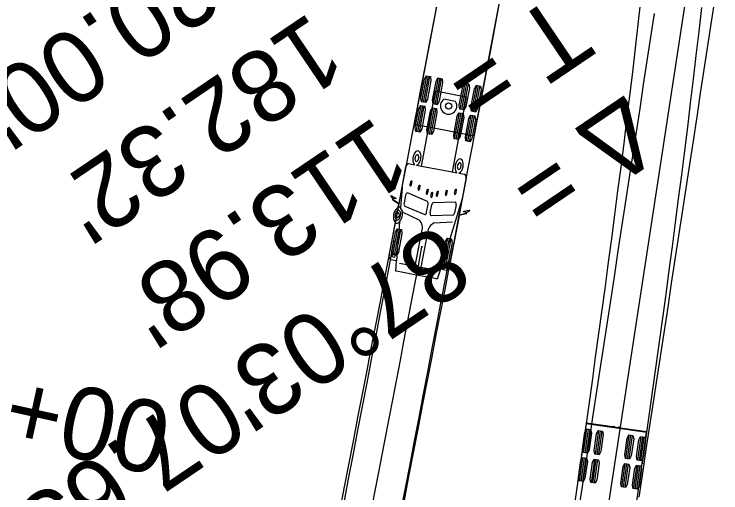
# Model space of a CAD drawing. Extents: x -69 to 14108008, y -6 to 8640172.
# Drawn here: x 14107816.5 to 14107914.7, y 8639651.1 to 8639717.5 of the extents above; entities that cross this region are included whole.
import ezdxf

# ---------------------------------------------------------------- set-up
doc = ezdxf.new("R2010")
doc.units = 0
for name, color, linetype in [('AutoTurn', 7, 'Continuous'), ('AutoTurn1', 7, 'Continuous'), ('AutoTurn2', 7, 'Continuous'), ('TextAlignment', 7, 'Continuous'), ('TextAlignmentSml', 7, 'Continuous')]:
    doc.layers.add(name, color=color, linetype=linetype)

msp = doc.modelspace()

# ---------------------------------------------------------------- linework, layer by layer
at = {"layer": 'AutoTurn'}
msp.add_arc((14098576.761, 8641447.78), 9462, 348.2293605, 349.264447, dxfattribs=at)
at = {"layer": 'AutoTurn1'}
for p, q in [((14107873.128, 8639705.357), (14107873.811, 8639708.959)), ((14107873.354, 8639705.314), (14107874.037, 8639708.916)), ((14107873.579, 8639705.271), (14107874.262, 8639708.874)), ((14107874.75, 8639705.049), (14107875.433, 8639708.652)), ((14107874.975, 8639705.007), (14107875.658, 8639708.609)), ((14107875.2, 8639704.964), (14107875.883, 8639708.566)), ((14107878.467, 8639704.345), (14107879.15, 8639707.947)), ((14107878.692, 8639704.302), (14107879.375, 8639707.904)), ((14107878.917, 8639704.259), (14107879.6, 8639707.862)), ((14107880.088, 8639704.037), (14107880.771, 8639707.64)), ((14107880.313, 8639703.995), (14107880.996, 8639707.597)), ((14107880.538, 8639703.952), (14107881.221, 8639707.554)), ((14107877.796, 8639705.42), (14107876.208, 8639705.721)), ((14107872.346, 8639701.23), (14107873.029, 8639704.833)), ((14107872.571, 8639701.187), (14107873.254, 8639704.79)), ((14107872.796, 8639701.145), (14107873.479, 8639704.747)), ((14107873.967, 8639700.923), (14107874.65, 8639704.525)), ((14107874.192, 8639700.88), (14107874.875, 8639704.483)), ((14107874.418, 8639700.837), (14107875.101, 8639704.44)), ((14107877.684, 8639700.218), (14107878.367, 8639703.821)), ((14107877.91, 8639700.175), (14107878.593, 8639703.778)), ((14107878.135, 8639700.133), (14107878.818, 8639703.735)), ((14107879.305, 8639699.911), (14107879.988, 8639703.513)), ((14107879.531, 8639699.868), (14107880.214, 8639703.471)), ((14107879.756, 8639699.825), (14107880.439, 8639703.428)), ((14107871.291, 8639696.782), (14107872.122, 8639696.625)), ((14107873.073, 8639696.444), (14107877.328, 8639695.638)), ((14107878.279, 8639695.457), (14107879.109, 8639695.3)), ((14107871.505, 8639693.868), (14107871.646, 8639694.401)), ((14107871.646, 8639694.401), (14107871.735, 8639694.384)), ((14107871.735, 8639694.384), (14107871.671, 8639693.837)), ((14107872.63, 8639693.263), (14107872.771, 8639693.795)), ((14107872.771, 8639693.795), (14107872.859, 8639693.779)), ((14107872.859, 8639693.779), (14107872.795, 8639693.231)), ((14107870.384, 8639693.454), (14107870.178, 8639690.655)), ((14107873.764, 8639692.707), (14107873.905, 8639693.24)), ((14107873.905, 8639693.24), (14107873.993, 8639693.223)), ((14107873.993, 8639693.223), (14107873.929, 8639692.676)), ((14107874.4, 8639692.273), (14107874.541, 8639692.805)), ((14107874.541, 8639692.805), (14107874.629, 8639692.789)), ((14107875.152, 8639692.444), (14107875.293, 8639692.977)), ((14107875.293, 8639692.977), (14107875.381, 8639692.96)), ((14107875.381, 8639692.96), (14107875.317, 8639692.413)), ((14107876.406, 8639692.521), (14107876.551, 8639693.079)), ((14107876.551, 8639693.079), (14107876.639, 8639693.062)), ((14107876.639, 8639693.062), (14107876.572, 8639692.49)), ((14107877.678, 8639692.698), (14107877.819, 8639693.231)), ((14107877.819, 8639693.231), (14107877.907, 8639693.214)), ((14107877.907, 8639693.214), (14107877.843, 8639692.667)), ((14107869.142, 8639691.932), (14107869.123, 8639691.952)), ((14107869.17, 8639691.928), (14107869.142, 8639691.932)), ((14107870.886, 8639692.391), (14107870.676, 8639691.28)), ((14107873.914, 8639691.537), (14107871.15, 8639692.717)), ((14107874.629, 8639692.789), (14107874.566, 8639692.241)), ((14107878.735, 8639691.871), (14107875.708, 8639682.13)), ((14107869.965, 8639691.244), (14107869.946, 8639691.145)), ((14107870.769, 8639690.885), (14107873.534, 8639689.705)), ((14107873.797, 8639690.032), (14107874.008, 8639691.143)), ((14107874.306, 8639689.935), (14107874.517, 8639691.046)), ((14107874.748, 8639691.379), (14107877.753, 8639691.466)), ((14107877.879, 8639691.065), (14107877.668, 8639689.954)), ((14107872.766, 8639688.943), (14107870.448, 8639690.03)), ((14107879.307, 8639690.006), (14107879.334, 8639689.999)), ((14107879.334, 8639689.999), (14107879.359, 8639690.011)), ((14107877.437, 8639689.621), (14107874.432, 8639689.535)), ((14107878.316, 8639689.66), (14107878.298, 8639689.562)), ((14107868.593, 8639684.008), (14107869.458, 8639688.571)), ((14107870.034, 8639688.693), (14107869.636, 8639683.281)), ((14107874.867, 8639688.544), (14107877.409, 8639688.706)), ((14107869.105, 8639684.135), (14107869.788, 8639687.737)), ((14107869.33, 8639684.092), (14107870.013, 8639687.695)), ((14107869.555, 8639684.049), (14107870.238, 8639687.652)), ((14107872.22, 8639682.562), (14107873.131, 8639687.367)), ((14107873.04, 8639682.406), (14107873.951, 8639687.212)), ((14107876.064, 8639682.815), (14107876.747, 8639686.418)), ((14107876.289, 8639682.773), (14107876.972, 8639686.375)), ((14107876.515, 8639682.73), (14107877.198, 8639686.332)), ((14107869.054, 8639684.242), (14107868.988, 8639683.892)), ((14107869.459, 8639684.165), (14107869.054, 8639684.242)), ((14107869.393, 8639683.815), (14107869.459, 8639684.165)), ((14107868.988, 8639683.892), (14107869.393, 8639683.815)), ((14107870.039, 8639682.975), (14107875.505, 8639681.939)), ((14107876.129, 8639682.538), (14107876.196, 8639682.888)), ((14107876.535, 8639682.461), (14107876.129, 8639682.538)), ((14107876.196, 8639682.888), (14107876.601, 8639682.811)), ((14107876.601, 8639682.811), (14107876.535, 8639682.461))]:
    msp.add_line(p, q, dxfattribs=at)
for points in [[(14107881.931, 8639754.235), (14107881.909, 8639754.239), (14107881.896, 8639754.17), (14107880.84, 8639748.602), (14107872.049, 8639702.236), (14107876.225, 8639701.445), (14107880.4, 8639700.653), (14107889.191, 8639747.019), (14107890.246, 8639752.587), (14107890.259, 8639752.656), (14107890.238, 8639752.66)], [(14107875.495, 8639720.425), (14107874.873, 8639717.152), (14107874.251, 8639713.879), (14107873.628, 8639710.606), (14107873.005, 8639707.333), (14107872.382, 8639704.061), (14107871.758, 8639700.788), (14107871.134, 8639697.516), (14107870.509, 8639694.244), (14107869.883, 8639690.972), (14107869.257, 8639687.7), (14107868.63, 8639684.428), (14107868.002, 8639681.157), (14107867.374, 8639677.886), (14107866.744, 8639674.615), (14107866.114, 8639671.344), (14107865.484, 8639668.073), (14107864.852, 8639664.802), (14107864.22, 8639661.532), (14107863.586, 8639658.262), (14107862.952, 8639654.992), (14107862.317, 8639651.722), (14107861.681, 8639648.453)], [(14107883.846, 8639718.839), (14107883.224, 8639715.565), (14107882.601, 8639712.291), (14107881.979, 8639709.017), (14107881.355, 8639705.744), (14107880.732, 8639702.47), (14107880.108, 8639699.196), (14107879.483, 8639695.922), (14107878.857, 8639692.648), (14107878.232, 8639689.375), (14107877.605, 8639686.101), (14107876.978, 8639682.828), (14107876.35, 8639679.555), (14107875.721, 8639676.281), (14107875.091, 8639673.008), (14107874.461, 8639669.735), (14107873.83, 8639666.462), (14107873.198, 8639663.19), (14107872.565, 8639659.917), (14107871.931, 8639656.645), (14107871.296, 8639653.372), (14107870.661, 8639650.1)], [(14107872.399, 8639696.572), (14107873.072, 8639696.444), (14107873.117, 8639696.678), (14107875.048, 8639706.859), (14107877.175, 8639706.455), (14107879.302, 8639706.052), (14107877.372, 8639695.872), (14107877.328, 8639695.638), (14107878.002, 8639695.51)], [(14107869.107, 8639691.866), (14107869.123, 8639691.951), (14107869.121, 8639691.954), (14107868.854, 8639692.247), (14107868.852, 8639692.249), (14107868.874, 8639692.366), (14107868.876, 8639692.366), (14107869.535, 8639691.979), (14107869.516, 8639691.878), (14107869.17, 8639691.928), (14107869.169, 8639691.927), (14107869.155, 8639691.848), (14107869.155, 8639691.847), (14107869.155, 8639691.847), (14107869.16, 8639691.809), (14107869.16, 8639691.808), (14107869.965, 8639691.244), (14107870.929, 8639696.329)], [(14107879.281, 8639694.746), (14107878.316, 8639689.66), (14107879.272, 8639689.891), (14107879.272, 8639689.892), (14107879.291, 8639689.925), (14107879.291, 8639689.926), (14107879.291, 8639689.927), (14107879.307, 8639690.005), (14107879.306, 8639690.006), (14107878.967, 8639690.086), (14107878.986, 8639690.188), (14107879.741, 8639690.306), (14107879.742, 8639690.305), (14107879.72, 8639690.189), (14107879.718, 8639690.187), (14107879.361, 8639690.012), (14107879.359, 8639690.01), (14107879.342, 8639689.926)], [(14107869.866, 8639690.719), (14107869.945, 8639691.137), (14107869.938, 8639691.151), (14107869.126, 8639691.727)], [(14107879.274, 8639689.803), (14107878.307, 8639689.564), (14107878.296, 8639689.554), (14107876.945, 8639682.424)], [(14107869.221, 8639685.979), (14107868.6, 8639682.705), (14107867.978, 8639679.432), (14107867.354, 8639676.16), (14107866.73, 8639672.888), (14107866.104, 8639669.616), (14107865.477, 8639666.344), (14107864.849, 8639663.073), (14107864.22, 8639659.802), (14107863.59, 8639656.531), (14107862.958, 8639653.26), (14107862.326, 8639649.99), (14107861.692, 8639646.72), (14107861.057, 8639643.45), (14107860.421, 8639640.181), (14107859.784, 8639636.912), (14107859.146, 8639633.642), (14107858.506, 8639630.374), (14107857.866, 8639627.105), (14107857.224, 8639623.837), (14107856.581, 8639620.569), (14107855.937, 8639617.301), (14107855.292, 8639614.033)], [(14107877.081, 8639684.488), (14107876.46, 8639681.214), (14107875.837, 8639677.94), (14107875.214, 8639674.666), (14107874.589, 8639671.393), (14107873.963, 8639668.119), (14107873.336, 8639664.845), (14107872.707, 8639661.572), (14107872.078, 8639658.299), (14107871.447, 8639655.026), (14107870.815, 8639651.753), (14107870.182, 8639648.48), (14107869.548, 8639645.208), (14107868.912, 8639641.935), (14107868.276, 8639638.663), (14107867.638, 8639635.391), (14107867, 8639632.12), (14107866.36, 8639628.848), (14107865.718, 8639625.577), (14107865.076, 8639622.306), (14107864.433, 8639619.035), (14107863.788, 8639615.765)], [(14107876.558, 8639681.968), (14107875.716, 8639682.128), (14107875.707, 8639682.128), (14107875.281, 8639680.759), (14107875.219, 8639680.77), (14107872.406, 8639681.304), (14107869.593, 8639681.837), (14107869.531, 8639681.849), (14107869.636, 8639683.279), (14107869.628, 8639683.282), (14107868.786, 8639683.442)]]:
    msp.add_lwpolyline(points, dxfattribs=at)
for points in [[(14107873.635, 8639705.261), (14107873.073, 8639705.367), (14107872.999, 8639705.904), (14107873.491, 8639708.497), (14107873.756, 8639708.97), (14107874.318, 8639708.863), (14107874.391, 8639708.327), (14107873.9, 8639705.733)], [(14107875.256, 8639704.953), (14107874.694, 8639705.06), (14107874.62, 8639705.596), (14107875.112, 8639708.19), (14107875.377, 8639708.662), (14107875.939, 8639708.556), (14107876.012, 8639708.019), (14107875.521, 8639705.426)], [(14107878.973, 8639704.249), (14107878.411, 8639704.355), (14107878.337, 8639704.892), (14107878.829, 8639707.485), (14107879.094, 8639707.958), (14107879.656, 8639707.851), (14107879.73, 8639707.315), (14107879.238, 8639704.721)], [(14107880.594, 8639703.941), (14107880.032, 8639704.048), (14107879.958, 8639704.584), (14107880.45, 8639707.178), (14107880.715, 8639707.65), (14107881.277, 8639707.544), (14107881.351, 8639707.007), (14107880.859, 8639704.413)], [(14107872.852, 8639701.134), (14107872.29, 8639701.241), (14107872.217, 8639701.777), (14107872.708, 8639704.371), (14107872.973, 8639704.843), (14107873.535, 8639704.737), (14107873.609, 8639704.2), (14107873.117, 8639701.606)], [(14107874.473, 8639700.827), (14107873.911, 8639700.933), (14107873.838, 8639701.47), (14107874.329, 8639704.064), (14107874.594, 8639704.536), (14107875.156, 8639704.429), (14107875.23, 8639703.893), (14107874.738, 8639701.299)], [(14107878.191, 8639700.122), (14107877.629, 8639700.229), (14107877.555, 8639700.765), (14107878.047, 8639703.359), (14107878.312, 8639703.831), (14107878.874, 8639703.725), (14107878.947, 8639703.188), (14107878.455, 8639700.594)], [(14107879.812, 8639699.815), (14107879.25, 8639699.921), (14107879.176, 8639700.458), (14107879.668, 8639703.052), (14107879.933, 8639703.524), (14107880.495, 8639703.417), (14107880.568, 8639702.881), (14107880.077, 8639700.287)], [(14107869.611, 8639684.039), (14107869.049, 8639684.145), (14107868.975, 8639684.682), (14107869.467, 8639687.276), (14107869.732, 8639687.748), (14107870.294, 8639687.641), (14107870.368, 8639687.105), (14107869.876, 8639684.511)], [(14107876.57, 8639682.719), (14107876.008, 8639682.826), (14107875.935, 8639683.362), (14107876.427, 8639685.956), (14107876.691, 8639686.428), (14107877.253, 8639686.322), (14107877.327, 8639685.785), (14107876.835, 8639683.192)]]:
    msp.add_lwpolyline(points, close=True, dxfattribs=at)
for centre, radius in [((14107876.856, 8639704.774), 0.424), ((14107869.221, 8639685.979), 0.0417), ((14107873.151, 8639685.234), 0.0417), ((14107877.081, 8639684.488), 0.0417)]:
    msp.add_circle(centre, radius, dxfattribs=at)
for centre, radius, start, end in [((14107876.851, 8639704.777), 1.143, 124.26445, 34.26445), ((14107873.3, 8639697.433), 1.416, 134.26844, 171.3363), ((14107872.845, 8639697.498), 0.664, 136.1389, 174.36062), ((14107872.56, 8639698.206), 0.346, 38.85869, 135.87175), ((14107872.496, 8639697.845), 0.172, 51.81225, 138.96284), ((14107872.346, 8639697.725), 0.362, 355.9269, 44.96789), ((14107871.882, 8639697.796), 1.136, 351.97974, 33.50048), ((14107871.537, 8639696.214), 0.619, 113.42476, 169.26647), ((14107872.997, 8639697.349), 1.136, 164.84322, 219.63451), ((14107872.693, 8639697.446), 0.522, 167.09496, 214.25908), ((14107872.389, 8639697.262), 0.169, 220.7114, 320.83012), ((14107872.138, 8639697.253), 0.729, 290.94196, 333.45596), ((14107871.977, 8639697.647), 0.732, 317.85619, 4.09062), ((14107871.282, 8639697.776), 1.73, 330.6393, 355.43781), ((14107879.482, 8639696.221), 1.73, 163.09109, 187.88959), ((14107878.931, 8639696.46), 1.136, 125.02841, 166.54916), ((14107878.473, 8639696.563), 0.362, 113.56101, 162.60199), ((14107878.45, 8639697.09), 0.346, 22.65715, 119.6702), ((14107878.378, 8639696.73), 0.172, 19.56605, 106.71664), ((14107877.925, 8639696.534), 0.664, 344.16828, 22.38999), ((14107877.478, 8639696.641), 1.416, 347.1926, 24.26045), ((14107878.494, 8639696.048), 0.729, 185.07293, 227.58693), ((14107878.787, 8639696.355), 0.732, 154.43827, 200.67271), ((14107878.263, 8639696.148), 0.169, 197.69877, 297.81749), ((14107877.73, 8639696.452), 1.136, 298.89438, 353.68568), ((14107878.048, 8639696.431), 0.522, 304.26981, 351.43394), ((14107878.672, 8639694.861), 0.619, 349.26242, 45.10413), ((14107871.639, 8639693.787), 0.157, 148.6088, 235.71847), ((14107871.487, 8639693.83), 0.184, 290.41925, 2.31127), ((14107872.764, 8639693.181), 0.157, 148.6088, 235.71847), ((14107872.611, 8639693.224), 0.184, 290.41925, 2.31127), ((14107869.18, 8639691.787), 0.108, 132.24078, 178.42327), ((14107871.218, 8639692.393), 0.332, 101.92104, 180.34304), ((14107873.898, 8639692.626), 0.157, 148.6088, 235.71847), ((14107873.745, 8639692.669), 0.184, 290.41925, 2.31127), ((14107874.534, 8639692.191), 0.157, 148.6088, 235.71847), ((14107874.411, 8639692.214), 0.157, 282.81043, 9.92009), ((14107875.32, 8639692.37), 0.184, 156.21763, 228.10964), ((14107875.163, 8639692.386), 0.157, 282.81043, 9.92009), ((14107876.579, 8639692.472), 0.184, 156.21763, 228.10964), ((14107876.421, 8639692.488), 0.157, 282.81043, 9.92009), ((14107877.847, 8639692.624), 0.184, 156.21763, 228.10964), ((14107877.689, 8639692.64), 0.157, 282.81043, 9.92009), ((14107869.123, 8639691.779), 0.0522, 168.14704, 273.00166), ((14107871.043, 8639691.158), 0.387, 161.69963, 224.9316), ((14107873.641, 8639691.264), 0.387, 341.70208, 44.92915), ((14107874.903, 8639691.025), 0.387, 113.59975, 176.82681), ((14107877.57, 8639691.188), 0.332, 338.18585, 56.60785), ((14107870.715, 8639689.444), 1.53, 123.75718, 214.76623), ((14107870.467, 8639689.521), 1.03, 142.0881, 170.47461), ((14107870.207, 8639689.543), 0.589, 142.01997, 185.00269), ((14107869.919, 8639689.98), 0.317, 85.11464, 146.70704), ((14107869.875, 8639689.799), 0.17, 86.93351, 140.99785), ((14107869.963, 8639690.383), 0.347, 51.59166, 106.40224), ((14107869.761, 8639689.737), 0.263, 348.19936, 62.10128), ((14107869.759, 8639689.896), 0.44, 1.05869, 64.87154), ((14107869.017, 8639689.774), 1.189, 330.39565, 6.28497), ((14107869.331, 8639689.898), 1.136, 347.96899, 41.77155), ((14107873.503, 8639689.999), 0.296, 275.98321, 6.28088), ((14107874.568, 8639689.797), 0.296, 152.24801, 242.54569), ((14107877.282, 8639689.975), 0.387, 293.5973, 356.82926), ((14107879.246, 8639689.878), 0.108, 340.10562, 26.28812), ((14107870.047, 8639689.473), 0.634, 159.84831, 235.85002), ((14107869.843, 8639689.478), 0.223, 176.49935, 246.10184), ((14107869.708, 8639689.313), 0.366, 267.31679, 339.79777), ((14107869.768, 8639689.431), 0.158, 264.23567, 325.74842), ((14107869.443, 8639689.694), 0.575, 322.33956, 358.90989), ((14107868.745, 8639689.807), 1.704, 319.18513, 355.0932), ((14107871.699, 8639687.865), 1.517, 340.84449, 45.27191), ((14107879.296, 8639689.85), 0.0522, 245.52723, 350.38185), ((14107869.691, 8639688.944), 0.425, 237.32738, 323.86374), ((14107875.466, 8639687.151), 1.517, 113.25699, 177.6844), ((14098576.761, 8641447.78), 9462, 348.2293605, 349.264447), ((14107869.052, 8639683.849), 0.486, 160.85038, 236.80148), ((14107876.459, 8639682.444), 0.486, 281.72741, 357.67852)]:
    msp.add_arc(centre, radius, start, end, dxfattribs=at)
for centre, major_axis, start_param, end_param in [((14107869.116, 8639691.796), (-0.0146, -0.0769), 2.398717, 3.668019), ((14107869.116, 8639691.796), (-0.0146, -0.0769), 0.569648, 1.840391), ((14107879.309, 8639689.863), (0.0146, 0.0769), 1.301202, 2.571945), ((14107879.309, 8639689.863), (-0.0146, -0.0769), 2.615166, 3.884468)]:
    msp.add_ellipse(centre, major_axis=major_axis, ratio=0.544872, start_param=start_param, end_param=end_param, dxfattribs=at)
at = {"layer": 'AutoTurn2'}
for p, q in [((14107922.677, 8639804.377), (14107890.191, 8639591.46)), ((14107895.936, 8639660.698), (14107904.352, 8639659.503)), ((14107895.599, 8639656.697), (14107896.063, 8639659.964)), ((14107895.826, 8639656.665), (14107896.29, 8639659.932)), ((14107896.053, 8639656.632), (14107896.517, 8639659.9)), ((14107897.233, 8639656.465), (14107897.697, 8639659.732)), ((14107897.46, 8639656.433), (14107897.924, 8639659.7)), ((14107897.687, 8639656.4), (14107898.151, 8639659.668)), ((14107899.628, 8639660.245), (14107899.891, 8639660.208)), ((14107900.41, 8639660.134), (14107899.894, 8639660.207)), ((14107900.154, 8639660.17), (14107900.144, 8639660.1)), ((14107900.417, 8639660.133), (14107900.68, 8639660.096)), ((14107901.474, 8639655.862), (14107901.938, 8639659.13)), ((14107901.701, 8639655.83), (14107902.165, 8639659.097)), ((14107901.928, 8639655.798), (14107902.392, 8639659.065)), ((14107903.107, 8639655.63), (14107903.571, 8639658.898)), ((14107903.334, 8639655.598), (14107903.798, 8639658.865)), ((14107903.561, 8639655.566), (14107904.025, 8639658.833)), ((14107895.037, 8639652.737), (14107895.501, 8639656.004)), ((14107895.264, 8639652.704), (14107895.728, 8639655.972)), ((14107895.491, 8639652.672), (14107895.955, 8639655.939)), ((14107896.67, 8639652.505), (14107897.135, 8639655.772)), ((14107896.897, 8639652.472), (14107897.361, 8639655.74)), ((14107897.124, 8639652.44), (14107897.588, 8639655.707)), ((14107900.911, 8639651.902), (14107901.375, 8639655.169)), ((14107901.138, 8639651.87), (14107901.602, 8639655.137)), ((14107901.365, 8639651.838), (14107901.829, 8639655.105)), ((14107902.545, 8639651.67), (14107903.009, 8639654.937)), ((14107902.772, 8639651.638), (14107903.236, 8639654.905)), ((14107902.999, 8639651.606), (14107903.463, 8639654.873))]:
    msp.add_line(p, q, dxfattribs=at)
for points in [[(14107903.503, 8639719.381), (14107903.133, 8639716.083), (14107902.754, 8639712.784), (14107902.367, 8639709.486), (14107901.971, 8639706.187), (14107901.568, 8639702.888), (14107901.158, 8639699.589), (14107900.741, 8639696.29), (14107900.318, 8639692.992), (14107899.89, 8639689.693), (14107899.456, 8639686.395), (14107899.017, 8639683.096), (14107898.574, 8639679.798), (14107898.127, 8639676.5), (14107897.676, 8639673.202), (14107897.221, 8639669.903), (14107896.763, 8639666.606), (14107896.301, 8639663.308), (14107895.837, 8639660.01), (14107895.37, 8639656.712), (14107895.323, 8639656.383)], [(14107913.809, 8639719.738), (14107913.306, 8639716.441), (14107912.803, 8639713.143), (14107912.3, 8639709.846), (14107911.797, 8639706.549), (14107911.294, 8639703.252), (14107910.791, 8639699.956), (14107910.288, 8639696.659), (14107909.785, 8639693.363), (14107909.282, 8639690.066), (14107908.779, 8639686.77), (14107908.276, 8639683.474), (14107907.773, 8639680.178), (14107907.27, 8639676.882), (14107906.768, 8639673.586), (14107906.265, 8639670.289), (14107905.762, 8639666.993), (14107905.259, 8639663.697), (14107904.756, 8639660.401), (14107904.253, 8639657.105), (14107903.75, 8639653.809), (14107903.247, 8639650.513)], [(14107911.951, 8639718.449), (14107911.579, 8639715.126), (14107911.198, 8639711.804), (14107910.808, 8639708.484), (14107910.409, 8639705.166), (14107910.004, 8639701.849), (14107909.592, 8639698.533), (14107909.173, 8639695.218), (14107908.748, 8639691.905), (14107908.318, 8639688.592), (14107907.883, 8639685.281), (14107907.443, 8639681.971), (14107906.998, 8639678.661), (14107906.549, 8639675.353), (14107906.097, 8639672.045), (14107905.641, 8639668.738), (14107905.181, 8639665.432), (14107904.719, 8639662.127), (14107904.254, 8639658.822), (14107903.786, 8639655.518), (14107903.739, 8639655.187)], [(14107905.395, 8639717.629), (14107904.892, 8639714.335), (14107904.39, 8639711.04), (14107903.887, 8639707.745), (14107903.384, 8639704.45), (14107902.881, 8639701.155), (14107902.379, 8639697.859), (14107901.876, 8639694.564), (14107901.373, 8639691.268), (14107900.87, 8639687.973), (14107900.367, 8639684.677), (14107899.864, 8639681.382), (14107899.362, 8639678.086), (14107898.859, 8639674.79), (14107898.356, 8639671.494), (14107897.853, 8639668.199), (14107897.35, 8639664.903), (14107896.847, 8639661.607), (14107896.344, 8639658.311), (14107895.842, 8639655.015), (14107895.339, 8639651.719), (14107894.836, 8639648.424)], [(14107895.968, 8639660.765), (14107895.947, 8639660.768), (14107895.937, 8639660.698), (14107895.139, 8639655.087), (14107888.502, 8639608.365), (14107892.71, 8639607.767), (14107896.918, 8639607.169), (14107903.555, 8639653.892), (14107904.351, 8639659.503), (14107904.361, 8639659.573), (14107904.34, 8639659.576)], [(14107899.904, 8639660.277), (14107899.639, 8639660.315), (14107899.638, 8639660.314), (14107899.628, 8639660.245), (14107899.593, 8639660.25), (14107895.993, 8639660.761), (14107895.992, 8639660.762)], [(14107904.316, 8639659.579), (14107904.315, 8639659.579), (14107900.715, 8639660.091), (14107900.68, 8639660.096), (14107900.69, 8639660.165), (14107900.688, 8639660.166), (14107900.424, 8639660.203)]]:
    msp.add_lwpolyline(points, dxfattribs=at)
for points in [[(14107896.109, 8639656.624), (14107895.543, 8639656.705), (14107895.437, 8639657.187), (14107895.772, 8639659.539), (14107896.007, 8639659.972), (14107896.574, 8639659.892), (14107896.679, 8639659.41), (14107896.345, 8639657.058)], [(14107897.743, 8639656.392), (14107897.177, 8639656.473), (14107897.071, 8639656.954), (14107897.405, 8639659.307), (14107897.641, 8639659.74), (14107898.207, 8639659.66), (14107898.313, 8639659.178), (14107897.979, 8639656.826)], [(14107901.984, 8639655.79), (14107901.417, 8639655.87), (14107901.312, 8639656.352), (14107901.646, 8639658.704), (14107901.882, 8639659.138), (14107902.448, 8639659.057), (14107902.554, 8639658.576), (14107902.219, 8639656.223)], [(14107903.617, 8639655.558), (14107903.051, 8639655.638), (14107902.945, 8639656.12), (14107903.28, 8639658.472), (14107903.515, 8639658.906), (14107904.081, 8639658.825), (14107904.187, 8639658.344), (14107903.853, 8639655.991)], [(14107895.547, 8639652.664), (14107894.981, 8639652.745), (14107894.875, 8639653.226), (14107895.209, 8639655.579), (14107895.445, 8639656.012), (14107896.011, 8639655.931), (14107896.117, 8639655.45), (14107895.782, 8639653.097)], [(14107897.18, 8639652.432), (14107896.614, 8639652.513), (14107896.509, 8639652.994), (14107896.843, 8639655.347), (14107897.078, 8639655.78), (14107897.645, 8639655.699), (14107897.75, 8639655.218), (14107897.416, 8639652.865)], [(14107901.421, 8639651.83), (14107900.855, 8639651.91), (14107900.749, 8639652.392), (14107901.083, 8639654.744), (14107901.319, 8639655.177), (14107901.885, 8639655.097), (14107901.991, 8639654.615), (14107901.657, 8639652.263)], [(14107903.055, 8639651.598), (14107902.489, 8639651.678), (14107902.383, 8639652.16), (14107902.717, 8639654.512), (14107902.953, 8639654.945), (14107903.519, 8639654.865), (14107903.625, 8639654.383), (14107903.29, 8639652.031)]]:
    msp.add_lwpolyline(points, close=True, dxfattribs=at)
for centre, radius in [((14107895.985, 8639660.797), 0.0266), ((14107904.333, 8639659.611), 0.0266), ((14107895.323, 8639656.383), 0.0417), ((14107903.739, 8639655.187), 0.0417)]:
    msp.add_circle(centre, radius, dxfattribs=at)
for centre, radius, start, end in [((14107896.253, 8639662.767), 2.022, 261.91521, 262.59897), ((14107899.898, 8639660.242), 0.0354, 86.20674, 258.39221), ((14107899.899, 8639660.242), 0.0352, 262.88953, 81.88994), ((14107900.419, 8639660.168), 0.0352, 81.94048, 260.94089), ((14107900.42, 8639660.168), 0.0353, 265.25139, 83.60104), ((14107904.333, 8639659.611), 0.0363, 280.99265, 242.154)]:
    msp.add_arc(centre, radius, start, end, dxfattribs=at)

# ---------------------------------------------------------------- texts
at = {"layer": 'TextAlignment'}
for s, p in [("120.00'", (14107846.628, 8639731.034)), ('T = ', (14107891.948, 8639720.561)), ("182.32'", (14107857.68, 8639717.946)), ('Δ = ', (14107901.492, 8639706.452)), ("113.98'", (14107866.713, 8639703.491)), ('87°03\'07.63"', (14107875.215, 8639688.677))]:
    msp.add_text(s, height=10.02, rotation=214.07711, dxfattribs=at).set_placement(p)
at = {"layer": 'TextAlignmentSml'}
msp.add_text('10293+00', height=10.02, rotation=347.60317, dxfattribs=at).set_placement((14107778.115, 8639666.262))

doc.saveas('drawing.dxf')
